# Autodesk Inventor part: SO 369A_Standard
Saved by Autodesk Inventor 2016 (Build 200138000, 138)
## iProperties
Created: 2012-01
Part Number: SO 369A_Standard
Document SubType Name: Modeling
Designer: Trevor
Density: 1 g/cm^3
Material: Generic
Appearance: Default
Author: Trevor
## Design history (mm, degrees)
feature "Base1"
node "Fase4"
